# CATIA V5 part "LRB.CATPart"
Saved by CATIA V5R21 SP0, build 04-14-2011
Part number: LRB.SLDPRT
Bounding box of the stored display mesh (mm): x 1.55 to 5.05, y 3.678 to 6.478, z -1.805 to -0.004
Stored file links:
  C:\Users\user\Desktop\CATIA文件\0-最新文件(2025.3月之前的慎用)\LRB\LRB.CATPart
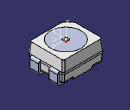
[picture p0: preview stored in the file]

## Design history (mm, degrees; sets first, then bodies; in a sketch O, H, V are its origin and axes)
AxisSystem1: origin (3.2993, 5.0728, -0.0046), X (0, -1, 0), Y (1, 0, 0), Z (0, 0, 1)
Set1
  DatumSurface1 to DatumSurface120
  Line1: stored without definition
  Circle1: stored without definition
  Line2: stored without definition
  Circle2: stored without definition
  Line3 to Line38: stored without definition
  Circle3: stored without definition
  Line39: stored without definition
  Circle4: stored without definition
  Line40 to Line43: stored without definition
  Circle5: stored without definition
  Circle6: stored without definition
  Line44 to Line46: stored without definition
  Circle7: stored without definition
  Line47: stored without definition
  Circle8: stored without definition
  Line48 to Line50: stored without definition
  Circle9 to Circle11: stored without definition
  Line51: stored without definition
  Circle12: stored without definition
  Line52: stored without definition
  Circle13 to Circle15: stored without definition
  Line53: stored without definition
  Circle16: stored without definition
  Line54: stored without definition
  Circle17 to Circle19: stored without definition
  Line55: stored without definition
  Circle20: stored without definition
  Line56: stored without definition
  Circle21 to Circle23: stored without definition
  Line57: stored without definition
  Circle24: stored without definition
  Line58: stored without definition
  Circle25: stored without definition
  Circle26: stored without definition
  Line59 to Line62: stored without definition
  Circle27: stored without definition
  Circle28: stored without definition
  Line63 to Line66: stored without definition
  Circle29: stored without definition
  Circle30: stored without definition
  Line67: stored without definition
  Circle31: stored without definition
  Line68: stored without definition
  Circle32: stored without definition
  Line69 to Line72: stored without definition
  Circle33: stored without definition
  Line73: stored without definition
  Circle34: stored without definition
  Circle35: stored without definition
  Line74: stored without definition
  Circle36: stored without definition
  Line75 to Line78: stored without definition
  Circle37: stored without definition
  Line79: stored without definition
  Circle38: stored without definition
  Line80 to Line82: stored without definition
  Circle39: stored without definition
  Line83: stored without definition
  Circle40: stored without definition
  Line84 to Line86: stored without definition
  Circle41: stored without definition
  Line87: stored without definition
  Circle42: stored without definition
  Line88 to Line90: stored without definition
  Circle43: stored without definition
  Line91: stored without definition
  Circle44: stored without definition
  Circle45: stored without definition
  Line92: stored without definition
  Circle46: stored without definition
  Line93 to Line95: stored without definition
  Circle47: stored without definition
  Line96: stored without definition
  Circle48: stored without definition
  Circle49: stored without definition
  Line97: stored without definition
  Circle50: stored without definition
  Line98 to Line100: stored without definition
  Circle51: stored without definition
  Line101: stored without definition
  Circle52: stored without definition
  Line102 to Line104: stored without definition
  Circle53: stored without definition
  Line105: stored without definition
  Circle54: stored without definition
  Line106 to Line108: stored without definition
  Circle55: stored without definition
  Line109: stored without definition
  Circle56: stored without definition
  Line110 to Line112: stored without definition
  Circle57: stored without definition
  Line113: stored without definition
  Circle58: stored without definition
  Line114: stored without definition
  Circle59: stored without definition
  Line115: stored without definition
  Circle60: stored without definition
  Line116 to Line118: stored without definition
  Circle61: stored without definition
  Line119: stored without definition
  Circle62: stored without definition
  Line120 to Line132: stored without definition
  Circle63: stored without definition
  Line133: stored without definition
  Circle64: stored without definition
  Line134 to Line136: stored without definition
  Circle65: stored without definition
  Line137: stored without definition
  Circle66: stored without definition
  Line138: stored without definition
  Circle67: stored without definition
  Line139: stored without definition
  Circle68: stored without definition
  Line140 to Line143: stored without definition
  Circle69: stored without definition
  Circle70: stored without definition
  Line144 to Line153: stored without definition
  Circle71: stored without definition
  Line154: stored without definition
  Circle72: stored without definition
  Line155 to Line157: stored without definition
  Circle73: stored without definition
  Line158: stored without definition
  Circle74: stored without definition
  Line159 to Line161: stored without definition
  Circle75: stored without definition
  Line162: stored without definition
  Circle76: stored without definition
  Line163 to Line165: stored without definition
  Circle77: stored without definition
  Line166: stored without definition
  Circle78: stored without definition
  Line167 to Line169: stored without definition
  Circle79: stored without definition
  Line170: stored without definition
  Circle80: stored without definition
  Line171 to Line173: stored without definition
  Circle81: stored without definition
  Line174: stored without definition
  Circle82: stored without definition
  Line175 to Line177: stored without definition
  Circle83: stored without definition
  Line178: stored without definition
  Circle84: stored without definition
  Line179 to Line181: stored without definition
  Circle85: stored without definition
  Line182: stored without definition
  Circle86: stored without definition
  Line183 to Line185: stored without definition
  Circle87: stored without definition
  Line186: stored without definition
  Circle88: stored without definition
  Line187 to Line189: stored without definition
  Circle89: stored without definition
  Line190: stored without definition
  Circle90: stored without definition
  Line191 to Line193: stored without definition
  Circle91: stored without definition
  Line194: stored without definition
  Circle92: stored without definition
  Line195 to Line197: stored without definition
  Circle93: stored without definition
  Line198: stored without definition
  Circle94: stored without definition
  Line199 to Line201: stored without definition
  Circle95: stored without definition
  Line202: stored without definition
  Circle96: stored without definition
  Line203 to Line205: stored without definition
  Circle97: stored without definition
  Line206: stored without definition
  Circle98: stored without definition
  Line207 to Line209: stored without definition
  Circle99: stored without definition
  Line210: stored without definition
  Circle100: stored without definition
  Line211 to Line213: stored without definition
  Circle101: stored without definition
  Line214: stored without definition
  Circle102: stored without definition
  Line215 to Line217: stored without definition
  Circle103: stored without definition
  Line218: stored without definition
  Circle104: stored without definition
  Line219 to Line221: stored without definition
  Circle105: stored without definition
  Line222: stored without definition
  Circle106: stored without definition
  Line223 to Line225: stored without definition
  Circle107: stored without definition
  Line226: stored without definition
  Circle108: stored without definition
  Line227 to Line229: stored without definition
  Circle109: stored without definition
  Line230: stored without definition
  Circle110: stored without definition
  Line231 to Line241: stored without definition
  DatumSurface121 to DatumSurface179
  Circle111: stored without definition
  Line242: stored without definition
  Circle112: stored without definition
  Line243: stored without definition
  Circle113 to Circle115: stored without definition
  Line244: stored without definition
  Circle116: stored without definition
  Line245 to Line248: stored without definition
  Circle117: stored without definition
  Circle118: stored without definition
  Line249 to Line251: stored without definition
  Circle119: stored without definition
  Line252: stored without definition
  Circle120: stored without definition
  Line253 to Line256: stored without definition
  Circle121: stored without definition
  Circle122: stored without definition
  Line257 to Line261: stored without definition
  Circle123: stored without definition
  Circle124: stored without definition
  Line262 to Line265: stored without definition
  Circle125 to Circle128: stored without definition
  Line266 to Line270: stored without definition
  Circle129: stored without definition
  Circle130: stored without definition
  Line271 to Line274: stored without definition
  Circle131: stored without definition
  Circle132: stored without definition
  Line275 to Line277: stored without definition
  Circle133: stored without definition
  Circle134: stored without definition
  Line278 to Line282: stored without definition
  Circle135: stored without definition
  Circle136: stored without definition
  Line283 to Line286: stored without definition
  Circle137: stored without definition
  Circle138: stored without definition
  Line287 to Line289: stored without definition
  Circle139: stored without definition
  Circle140: stored without definition
  Line290 to Line293: stored without definition
  Circle141: stored without definition
  Circle142: stored without definition
  Line294 to Line298: stored without definition
  Circle143: stored without definition
  Circle144: stored without definition
  Line299 to Line302: stored without definition
  Circle145: stored without definition
  Circle146: stored without definition
  Line303 to Line306: stored without definition
  Circle147: stored without definition
  Circle148: stored without definition
  Line307 to Line310: stored without definition
  Circle149: stored without definition
  Circle150: stored without definition
  Line311: stored without definition
  Circle151: stored without definition
  Line312: stored without definition
  Circle152 to Circle154: stored without definition
  Line313 to Line316: stored without definition
  Circle155: stored without definition
  Circle156: stored without definition
  Line317 to Line320: stored without definition
  Circle157: stored without definition
  Circle158: stored without definition
  Line321: stored without definition
  Line322: stored without definition
  Circle159: stored without definition
  Circle160: stored without definition
  Line323 to Line325: stored without definition
  Circle161: stored without definition
  Circle162: stored without definition
  Line326 to Line330: stored without definition
  Circle163: stored without definition
  Circle164: stored without definition
  Line331 to Line334: stored without definition
  Circle165: stored without definition
  Circle166: stored without definition
  Line335 to Line337: stored without definition
  Circle167: stored without definition
  Circle168: stored without definition
  Line338 to Line342: stored without definition
  Circle169: stored without definition
  Line343 to Line345: stored without definition
  Circle170: stored without definition
  Line346 to Line352: stored without definition
  DatumSurface180 to DatumSurface390
  Circle171: stored without definition
  Circle172: stored without definition
  Line353: stored without definition
  Line354: stored without definition
  Circle173: stored without definition
  Circle174: stored without definition
  DatumCurve1
  Line355: stored without definition
  Line356: stored without definition
  Circle175: stored without definition
  Line357: stored without definition
  DatumCurve2
  Circle176: stored without definition
  Line358: stored without definition
  Circle177 to Circle183: stored without definition
  Line359: stored without definition
  Line360: stored without definition
  Circle184 to Circle188: stored without definition
  Line361: stored without definition
  Circle189: stored without definition
  Line362: stored without definition
  Circle190 to Circle192: stored without definition
  Line363: stored without definition
  Circle193: stored without definition
  Line364: stored without definition
  Circle194 to Circle196: stored without definition
  Line365: stored without definition
  Circle197: stored without definition
  Line366: stored without definition
  Circle198 to Circle200: stored without definition
  Line367: stored without definition
  Circle201: stored without definition
  Line368: stored without definition
  Circle202 to Circle204: stored without definition
  Line369 to Line373: stored without definition
  Circle205: stored without definition
  Line374: stored without definition
  Circle206 to Circle208: stored without definition
  Line375: stored without definition
  Circle209: stored without definition
  Line376: stored without definition
  Circle210: stored without definition
  Line377 to Line379: stored without definition
  Circle211: stored without definition
  Circle212: stored without definition
  Line380 to Line383: stored without definition
  Circle213: stored without definition
  Circle214: stored without definition
  Line384 to Line388: stored without definition
  Circle215: stored without definition
  Circle216: stored without definition
  Line389 to Line391: stored without definition
  Circle217: stored without definition
  Circle218: stored without definition
  Line392: stored without definition
  Line393: stored without definition
  Circle219: stored without definition
  Circle220: stored without definition
  Line394 to Line397: stored without definition
  Circle221: stored without definition
  Circle222: stored without definition
  Line398 to Line401: stored without definition
  Circle223 to Circle226: stored without definition
  Line402 to Line405: stored without definition
  Circle227: stored without definition
  Circle228: stored without definition
  Line406 to Line409: stored without definition
  Circle229: stored without definition
  Circle230: stored without definition
  Line410 to Line413: stored without definition
  Circle231: stored without definition
  Circle232: stored without definition
  Line414 to Line417: stored without definition
  Circle233: stored without definition
  Circle234: stored without definition
  Line418 to Line422: stored without definition
  Circle235: stored without definition
  Circle236: stored without definition
  Line423 to Line426: stored without definition
  Circle237: stored without definition
  Circle238: stored without definition
  Line427 to Line429: stored without definition
  Circle239: stored without definition
  Circle240: stored without definition
  Line430 to Line433: stored without definition
  Circle241: stored without definition
  Circle242: stored without definition
  Line434 to Line438: stored without definition
  Circle243: stored without definition
  Circle244: stored without definition
  Line439 to Line441: stored without definition
  Circle245: stored without definition
  Circle246: stored without definition
  Line442 to Line445: stored without definition
  Circle247: stored without definition
  Circle248: stored without definition
  Line446 to Line450: stored without definition
  Circle249 to Circle252: stored without definition
  Line451 to Line454: stored without definition
  Circle253: stored without definition
  Circle254: stored without definition
  Line455 to Line459: stored without definition
  Circle255 to Circle257: stored without definition
  Line460: stored without definition
  Circle258: stored without definition
  Line461 to Line464: stored without definition
  Circle259: stored without definition
  Line465: stored without definition
  Circle260: stored without definition
  Line466 to Line468: stored without definition
  Circle261: stored without definition
  Line469: stored without definition
  Circle262: stored without definition
  Line470 to Line472: stored without definition
  Circle263: stored without definition
  Line473: stored without definition
  Circle264: stored without definition
  Line474 to Line476: stored without definition
  Circle265: stored without definition
  Line477: stored without definition
  Circle266: stored without definition
  Line478 to Line480: stored without definition
  Circle267: stored without definition
  Line481: stored without definition
  Circle268: stored without definition
  Line482 to Line484: stored without definition
  Circle269: stored without definition
  Line485: stored without definition
  Circle270: stored without definition
  Line486 to Line488: stored without definition
  Circle271: stored without definition
  Line489: stored without definition
  Circle272: stored without definition
  Line490 to Line492: stored without definition
  Circle273: stored without definition
  Line493: stored without definition
  Circle274: stored without definition
  Line494 to Line496: stored without definition
  Circle275: stored without definition
  Line497: stored without definition
  Circle276: stored without definition
  Line498 to Line500: stored without definition
  Circle277: stored without definition
  Line501: stored without definition
  Circle278: stored without definition
  Line502 to Line509: stored without definition
  Circle279: stored without definition
  Circle280: stored without definition
  DatumCurve3
  DatumCurve4
  Circle281: stored without definition
  Line510 to Line512: stored without definition
  DatumCurve5
  Circle282: stored without definition
  Circle283: stored without definition
  DatumCurve6
  DatumCurve7
  Line513: stored without definition
  DatumCurve8
  Line514: stored without definition
  Circle284: stored without definition
  DatumCurve9
  Circle285: stored without definition
  Line515: stored without definition
  Circle286: stored without definition
  Line516: stored without definition
  DatumCurve10
  Circle287: stored without definition
  Circle288: stored without definition
  Line517: stored without definition
  Line518: stored without definition
  DatumCurve11
  Circle289: stored without definition
  DatumCurve12
  Line519: stored without definition
  Circle290: stored without definition
  Line520: stored without definition
  DatumCurve13
  Circle291: stored without definition
  Line521: stored without definition
  Circle292: stored without definition
  Line522: stored without definition
  Line523: stored without definition
  Circle293: stored without definition
  Line524: stored without definition
  DatumCurve14
  Circle294: stored without definition
  Line525: stored without definition
  Line526: stored without definition
  Circle295: stored without definition
  Circle296: stored without definition
  Line527 to Line529: stored without definition
  DatumCurve15
  Line530: stored without definition
  Circle297: stored without definition
  DatumCurve16
  Line531: stored without definition
  Circle298: stored without definition
  Line532: stored without definition
  Line533: stored without definition
  DatumCurve17
  Circle299: stored without definition
  Line534: stored without definition
  Line535: stored without definition
  Circle300: stored without definition
  Circle301: stored without definition
  Line536: stored without definition
  Line537: stored without definition
  Circle302: stored without definition
  Line538: stored without definition
  Circle303: stored without definition
  Line539 to Line542: stored without definition
  DatumCurve18
  Line543: stored without definition
  DatumCurve19
  Circle304: stored without definition
  DatumCurve20
  Line544: stored without definition
  Circle305: stored without definition
  Line545: stored without definition
  DatumCurve21
  DatumCurve22
  Line546: stored without definition
  Circle306 to Circle308: stored without definition
  Line547: stored without definition
  Circle309: stored without definition
  Line548: stored without definition
  Line549: stored without definition
  DatumCurve23
  Line550 to Line555: stored without definition
  Circle310: stored without definition
  Line556: stored without definition
  Circle311: stored without definition
  Line557 to Line559: stored without definition
  Circle312: stored without definition
  Line560: stored without definition
  Circle313: stored without definition
  Line561 to Line580: stored without definition
  Circle314: stored without definition
  Line581: stored without definition
  DatumCurve24
  Line582: stored without definition
  DatumCurve25
  Line583 to Line588: stored without definition
  Circle315: stored without definition
  Line589: stored without definition
  Circle316: stored without definition
  Line590 to Line592: stored without definition
  Circle317: stored without definition
  Line593: stored without definition
  Circle318: stored without definition
  Line594 to Line596: stored without definition
  Circle319: stored without definition
  Line597: stored without definition
  Circle320: stored without definition
  Line598 to Line600: stored without definition
  Circle321: stored without definition
  Line601: stored without definition
  Circle322: stored without definition
  Line602 to Line604: stored without definition
  Circle323: stored without definition
  Line605: stored without definition
  Circle324: stored without definition
  Circle325: stored without definition
  Line606: stored without definition
  Circle326: stored without definition
  Line607 to Line609: stored without definition
  Circle327: stored without definition
  Line610: stored without definition
  Circle328: stored without definition
  Circle329: stored without definition
  Line611: stored without definition
  Circle330: stored without definition
  Line612 to Line614: stored without definition
  Circle331: stored without definition
  Line615: stored without definition
  Circle332: stored without definition
  Line616 to Line618: stored without definition
  Circle333: stored without definition
  Line619: stored without definition
  Circle334: stored without definition
  Line620 to Line622: stored without definition
  Circle335: stored without definition
  Line623: stored without definition
  Circle336: stored without definition
  Line624 to Line626: stored without definition
  Circle337: stored without definition
  Line627: stored without definition
  Circle338: stored without definition
  Line628 to Line634: stored without definition
  Circle339: stored without definition
  DatumCurve26
  Line635: stored without definition
  DatumCurve27
  Line636: stored without definition
  Line637: stored without definition
  DatumCurve28
  Line638: stored without definition
  DatumCurve29
  Circle340: stored without definition
  Line639: stored without definition
  DatumCurve30
  Line640 to Line642: stored without definition
  DatumCurve31
  Line643 to Line645: stored without definition
  DatumCurve32
  Circle341: stored without definition
  Line646 to Line650: stored without definition
  DatumCurve33
  Circle342: stored without definition
  Line651 to Line664: stored without definition
  Circle343: stored without definition
  Line665: stored without definition
  Circle344: stored without definition
  Line666: stored without definition
  Circle345: stored without definition
  Line667: stored without definition
  Circle346: stored without definition
  Line668: stored without definition
  Circle347: stored without definition
  Line669: stored without definition
  Circle348: stored without definition
  Line670: stored without definition
  Circle349: stored without definition
  DatumCurve34
  Line671 to Line674: stored without definition
  Circle350: stored without definition
  Line675 to Line677: stored without definition
  Circle351: stored without definition
  Line678: stored without definition
  Line679: stored without definition
  Circle352: stored without definition
  Line680 to Line683: stored without definition
  Circle353: stored without definition
  Line684: stored without definition
  Line685: stored without definition
  Circle354: stored without definition
  Line686 to Line688: stored without definition
  Circle355: stored without definition
  Line689 to Line692: stored without definition
  Circle356: stored without definition
  Line693 to Line702: stored without definition
  DatumCurve35
  Line703: stored without definition
  DatumCurve36
  Circle357: stored without definition
  Line704: stored without definition
  Line705: stored without definition
  Circle358: stored without definition
  Line706 to Line713: stored without definition
  Point1 "发光中心&几何中心（测试原点）": type Between, FirstPoint vertex [face of DatumSurface390], SecondPoint vertex [face of DatumSurface390], Ratio 0.5
  Point2 "虚拟坐标": (-0.0224, -0.004, -0.1576), relative to Point1, in AxisSystem1
Body1 (main body)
